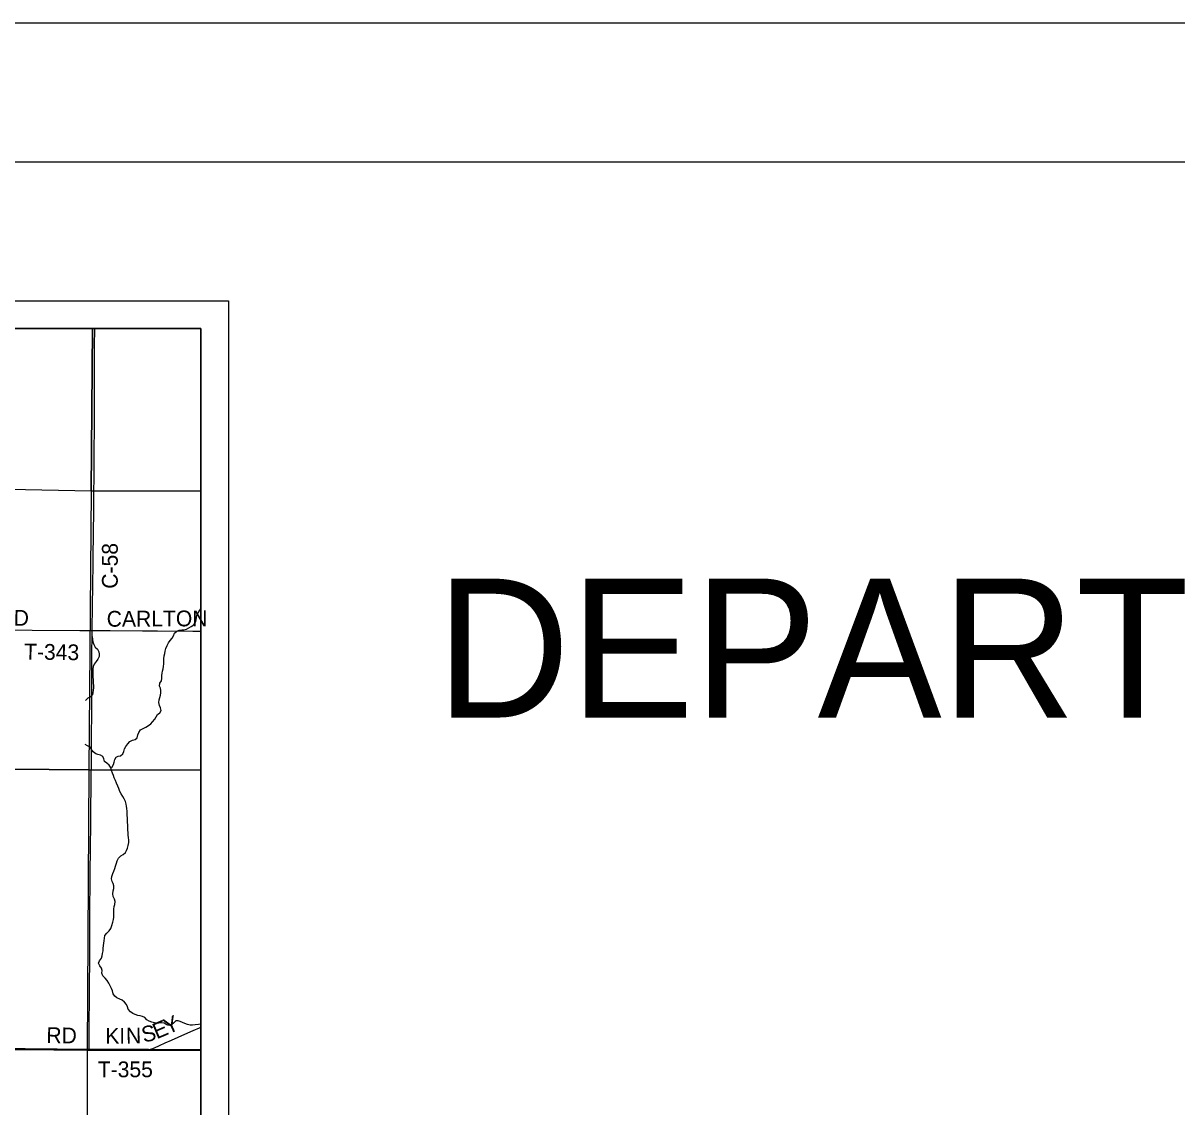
# Model space of a CAD drawing. Extents: x 0 to 34, y 0 to 22.
# Drawn here: x 8.26 to 12.415, y 18.098 to 22 of the extents above; entities that cross this region are included whole.
import ezdxf

# ---------------------------------------------------------------- set-up
doc = ezdxf.new("R2010")
doc.units = 0
for name, color, linetype in [('GM_X_Corporation', 7, 'Continuous'), ('GM_X_County_Road', 7, 'Continuous'), ('GM_X_County_Road_Text', 7, 'Continuous'), ('GM_X_Minor_River', 7, 'Continuous'), ('GM_X_Township_Road', 7, 'Continuous'), ('GM_X_Township_Road_Text', 7, 'Continuous'), ('SH_Border', 7, 'Continuous'), ('SH_Cut_Line', 7, 'Continuous'), ('SH_Data', 7, 'Continuous'), ('SH_Text', 7, 'Continuous')]:
    doc.layers.add(name, color=color, linetype=linetype)

msp = doc.modelspace()

# ---------------------------------------------------------------- linework, layer by layer
at = {"layer": 'GM_X_Corporation'}
for points in [[(7.581, 18.3149), (8.4971, 18.3046), (8.7111, 18.3046), (8.9, 18.3034), (8.9, 20.9), (3.5231, 20.9)], [(3.4463, 14.1), (8.9, 14.1), (8.9, 18.3034), (8.7111, 18.3046), (8.4971, 18.3046), (7.581, 18.3149)]]:
    msp.add_lwpolyline(points, dxfattribs=at)
for points in [[(8.5096, 20.9), (7.5063, 20.9), (7.5004, 20.336), (8.5046, 20.316)], [(8.9, 20.3154), (8.9, 20.9), (8.5096, 20.9), (8.5046, 20.316)], [(7.5004, 20.336), (8.5046, 20.316), (8.496, 19.3116), (7.4935, 19.3206)], [(8.9, 19.3101), (8.9, 20.3154), (8.5046, 20.316), (8.496, 19.3116)], [(8.496, 19.3116), (8.4911, 18.3026), (7.4788, 18.3152), (7.4935, 19.3206)], [(8.9, 18.3013), (8.9, 19.3101), (8.496, 19.3116), (8.4911, 18.3026)], [(8.4911, 18.3026), (8.489, 17.2189), (7.4742, 17.2327), (7.4788, 18.3152)], [(8.9, 17.211), (8.9, 18.3013), (8.4911, 18.3026), (8.489, 17.2189)]]:
    msp.add_lwpolyline(points, close=True, dxfattribs=at)
at = {"layer": 'GM_X_County_Road'}
for points in [[(8.4974, 18.3036), (8.4977, 18.3341), (8.4974, 18.4079), (8.4984, 18.4774), (8.4993, 18.553), (8.4997, 18.6101), (8.5005, 18.7008), (8.5007, 18.7684), (8.5017, 18.9478), (8.5022, 19.0211), (8.5036, 19.1274), (8.5042, 19.1783), (8.5048, 19.2448), (8.5058, 19.3765), (8.5063, 19.4187), (8.5066, 19.4603), (8.5068, 19.4895), (8.5069, 19.5478), (8.5071, 19.6242), (8.5076, 19.7124), (8.508, 19.8136), (8.51, 19.905), (8.5113, 19.9733), (8.5122, 20.0571), (8.5137, 20.1833), (8.5143, 20.2249), (8.5145, 20.2528), (8.5149, 20.3112), (8.5152, 20.3647), (8.5158, 20.4672), (8.5164, 20.5343), (8.5172, 20.625), (8.5173, 20.661), (8.5174, 20.8362), (8.5176, 20.9)], [(8.508, 19.8136), (8.573, 19.8131), (8.6902, 19.8126), (8.7438, 19.8118), (8.8711, 19.8108), (8.9, 19.8106)], [(7.7635, 18.3119), (7.8443, 18.3108), (7.9909, 18.3088), (8.1083, 18.3072), (8.2171, 18.3055), (8.3711, 18.3042), (8.4581, 18.3034), (8.4974, 18.3036)]]:
    msp.add_lwpolyline(points, dxfattribs=at)
at = {"layer": 'GM_X_Minor_River'}
for points in [[(8.5792, 19.3207), (8.5851, 19.3305), (8.5883, 19.3395), (8.5901, 19.3494), (8.5944, 19.3572), (8.6025, 19.3605), (8.6105, 19.3626), (8.6186, 19.3692), (8.6226, 19.3775), (8.6255, 19.3869), (8.6294, 19.3956), (8.6365, 19.4049), (8.6447, 19.4135), (8.6535, 19.4182), (8.6631, 19.4211), (8.6712, 19.427), (8.6733, 19.4372), (8.6769, 19.4458), (8.6824, 19.4552), (8.692, 19.4611), (8.7013, 19.4658), (8.7109, 19.4709), (8.7197, 19.4772), (8.7264, 19.485), (8.7342, 19.494), (8.7386, 19.503), (8.7437, 19.5112), (8.7518, 19.5175), (8.7565, 19.5254), (8.7544, 19.5349), (8.7512, 19.5438), (8.7484, 19.5537), (8.7494, 19.5636), (8.7519, 19.5726), (8.7543, 19.5806), (8.7556, 19.5889), (8.7562, 19.5969), (8.7549, 19.6053), (8.7512, 19.6133), (8.7518, 19.6232), (8.7585, 19.6322), (8.7598, 19.6409), (8.7597, 19.6515), (8.7606, 19.6595), (8.7623, 19.6674), (8.764, 19.6758), (8.7653, 19.6837), (8.7667, 19.6928), (8.7661, 19.7023), (8.7667, 19.7115), (8.7684, 19.7217), (8.7698, 19.73), (8.7715, 19.7395), (8.7743, 19.7485), (8.7788, 19.7595), (8.7835, 19.7685), (8.789, 19.7771), (8.7964, 19.7861), (8.8019, 19.7947), (8.8056, 19.8034), (8.8133, 19.8112), (8.8217, 19.814), (8.8309, 19.8153), (8.8389, 19.8163), (8.8481, 19.8184), (8.8569, 19.8231), (8.8654, 19.8283), (8.8746, 19.8341), (8.8809, 19.8431), (8.883, 19.8514), (8.8839, 19.8598), (8.8852, 19.8689), (8.89, 19.8775), (8.8967, 19.8869), (8.9, 19.8932)], [(8.5086, 19.7914), (8.5096, 19.7827), (8.5112, 19.7727), (8.5144, 19.7628), (8.5199, 19.7539), (8.5274, 19.7458), (8.5325, 19.7361), (8.5338, 19.7277), (8.5332, 19.7194), (8.5292, 19.71), (8.523, 19.7018), (8.5159, 19.692), (8.5123, 19.6841), (8.5114, 19.6754), (8.5108, 19.6674), (8.5106, 19.6583), (8.5108, 19.6503), (8.5119, 19.632), (8.5125, 19.6237), (8.5131, 19.6149), (8.5133, 19.6069), (8.5127, 19.5989), (8.5114, 19.5895), (8.5097, 19.5815), (8.5019, 19.5737), (8.4931, 19.5694), (8.4846, 19.5619)], [(8.5865, 18.8939), (8.584, 18.9023), (8.58, 18.9103), (8.5776, 18.9195), (8.5789, 18.9282), (8.5829, 18.938), (8.5862, 18.9467), (8.5898, 18.9565), (8.593, 18.9655), (8.5963, 18.9753), (8.5991, 18.9836), (8.6039, 18.9938), (8.6121, 19.0016), (8.6202, 19.0075), (8.6287, 19.0137), (8.6326, 19.0216), (8.6359, 19.0303), (8.6387, 19.0389), (8.6401, 19.0499), (8.6403, 19.059), (8.639, 19.0682), (8.638, 19.0766), (8.6378, 19.0865), (8.6373, 19.0945), (8.6371, 19.1024), (8.6369, 19.1127), (8.6364, 19.1233), (8.6362, 19.134), (8.6351, 19.1523), (8.6342, 19.1625), (8.6333, 19.1721), (8.6319, 19.1804), (8.6306, 19.1885), (8.6289, 19.1972), (8.6238, 19.2072), (8.6186, 19.2153), (8.6128, 19.225), (8.6084, 19.2342), (8.6041, 19.2442), (8.6005, 19.2526), (8.5962, 19.2633), (8.5922, 19.2733), (8.5882, 19.2829), (8.585, 19.2913), (8.5814, 19.3002), (8.5785, 19.3093), (8.5768, 19.3181), (8.5702, 19.3285), (8.5617, 19.3356), (8.5531, 19.3422), (8.5502, 19.3514), (8.5466, 19.3598), (8.538, 19.3642), (8.5293, 19.3671), (8.5214, 19.3699), (8.5124, 19.3762), (8.5065, 19.3847), (8.501, 19.3932), (8.4916, 19.398), (8.483, 19.4027)], [(8.9, 18.3956), (8.892, 18.395), (8.8798, 18.3942), (8.8703, 18.3929), (8.8612, 18.3927), (8.8513, 18.3944), (8.8423, 18.3984), (8.8344, 18.4017), (8.8257, 18.4053), (8.8178, 18.4085), (8.8095, 18.4083), (8.8017, 18.4001), (8.7936, 18.3942), (8.7852, 18.3917), (8.7772, 18.3938), (8.7675, 18.3994), (8.758, 18.4011), (8.7489, 18.4002), (8.7409, 18.4003), (8.733, 18.4013), (8.7235, 18.403), (8.7141, 18.407), (8.7059, 18.4122), (8.6977, 18.4203), (8.6894, 18.4243), (8.6815, 18.426), (8.6731, 18.4277), (8.6633, 18.4306), (8.6555, 18.4349), (8.6465, 18.4405), (8.6387, 18.4501), (8.6355, 18.4589), (8.6319, 18.4674), (8.6252, 18.4759), (8.617, 18.4821), (8.6076, 18.4865), (8.5978, 18.4906), (8.5896, 18.4964), (8.5841, 18.5057), (8.582, 18.5156), (8.5784, 18.5248), (8.5737, 18.534), (8.5686, 18.544), (8.5631, 18.5529), (8.5549, 18.5622), (8.5464, 18.5707), (8.5428, 18.5795), (8.5441, 18.5894), (8.5424, 18.5978), (8.5361, 18.6063), (8.5314, 18.6159), (8.5354, 18.6242), (8.5424, 18.6339), (8.5445, 18.6418), (8.5462, 18.6509), (8.5476, 18.66), (8.5485, 18.6691), (8.5499, 18.6789), (8.5508, 18.6876), (8.5518, 18.6967), (8.5524, 18.7062), (8.5545, 18.7149), (8.5611, 18.7235), (8.5697, 18.7316), (8.5755, 18.7403), (8.5796, 18.7516), (8.5833, 18.7636), (8.585, 18.7735), (8.586, 18.7818), (8.5865, 18.7909), (8.587, 18.8099), (8.5883, 18.8194), (8.59, 18.8273), (8.591, 18.8375), (8.5885, 18.8459), (8.5838, 18.8559), (8.5825, 18.8651), (8.5846, 18.8757), (8.5863, 18.8844), (8.5865, 18.8939)]]:
    msp.add_lwpolyline(points, dxfattribs=at)
at = {"layer": 'GM_X_Township_Road'}
for points in [[(8.1194, 19.8161), (8.4646, 19.8139), (8.508, 19.8136)], [(8.7035, 18.3039), (8.7069, 18.304), (8.7132, 18.3048), (8.718, 18.3058), (8.7239, 18.3077), (8.7326, 18.3111), (8.7508, 18.319), (8.7711, 18.3284), (8.7938, 18.3386), (8.8421, 18.3599), (8.8723, 18.373), (8.8952, 18.3828), (8.9, 18.3852)], [(8.4974, 18.3036), (8.5765, 18.3032), (8.6821, 18.3033), (8.6976, 18.3036), (8.7035, 18.3039)]]:
    msp.add_lwpolyline(points, dxfattribs=at)
at = {"layer": 'SH_Border'}
msp.add_lwpolyline([(1.5, 21.5), (33.5, 21.5), (33.5, 0.5), (1.5, 0.5)], close=True, dxfattribs=at)
at = {"layer": 'SH_Cut_Line'}
msp.add_lwpolyline([(0, 0), (34, 0), (34, 22), (0, 22)], close=True, dxfattribs=at)
at = {"layer": 'SH_Data'}
for p, q in [((2, 21), (9, 21)), ((9, 21), (9, 14)), ((2.1, 20.9), (8.9, 20.9)), ((2.1, 20.9), (8.9, 20.9)), ((2.1, 20.9), (8.9, 20.9)), ((8.9, 20.9), (8.9, 14.1)), ((8.9, 20.9), (8.9, 14.1)), ((8.9, 20.9), (8.9, 14.1))]:
    msp.add_line(p, q, dxfattribs=at)

# ---------------------------------------------------------------- texts
at = {"layer": 'GM_X_County_Road_Text'}
for s, rotation, p in [('C-58', 90, (8.6007, 19.9637)), ('CARLTON', 0.2907, (8.561, 19.8269)), ('RD', 359.0128, (8.3432, 18.3285))]:
    msp.add_text(s, height=0.05682, rotation=rotation, dxfattribs=at).set_placement(p)
at = {"layer": 'GM_X_Township_Road_Text'}
for s, height, rotation, p in [('RD', 0.05682, 359.0128, (8.1707, 19.8319)), ('T-343', 0.05682, 359.1569, (8.263, 19.7092)), ('E', 0.0568, 23.1017, (8.7411, 18.3414)), ('Y', 0.0568, 23.5175, (8.7806, 18.3582)), ('K', 0.0568, 0, (8.5561, 18.326)), ('I', 0.0568, 0, (8.6061, 18.326)), ('N', 0.0568, 1.4921, (8.6311, 18.3261)), ('S', 0.0568, 13.6577, (8.6941, 18.3291)), ('T-355', 0.05682, 0, (8.5287, 18.2051))]:
    msp.add_text(s, height=height, rotation=rotation, dxfattribs=at).set_placement(p)
at = {"layer": 'SH_Text'}
msp.add_text('DEPARTMENT OF TRANSPORTATION', height=0.5, dxfattribs=at).set_placement((9.7466, 19.5))

doc.saveas('drawing.dxf')
